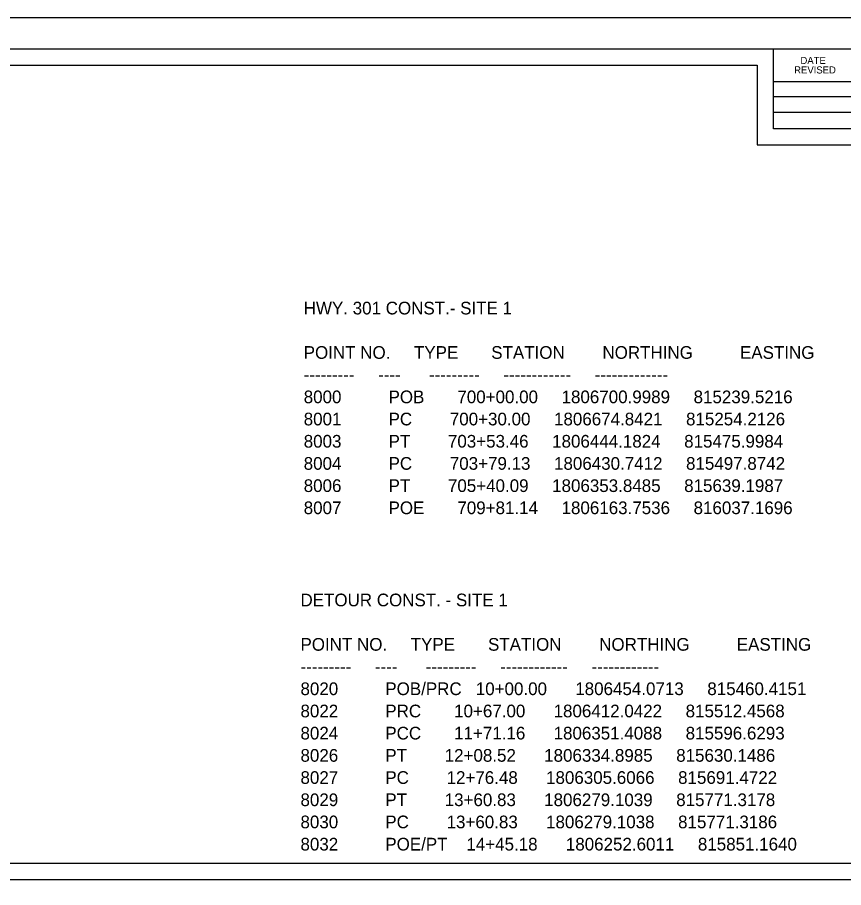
# Model space of a CAD drawing. Extents: x 818639 to 819473, y 1805980 to 1806194.
# Drawn here: x 818811.6 to 818913.8, y 1806086 to 1806193.7 of the extents above; entities that cross this region are included whole.
import ezdxf

# ---------------------------------------------------------------- set-up
doc = ezdxf.new("R2010")
doc.units = 0
for name, color, linetype in [('R_Border', 7, 'Continuous'), ('R_Border Plan-Plan', 7, 'Continuous'), ('R_Draft', 7, 'Continuous'), ('R_No Plot', 7, 'Continuous')]:
    doc.layers.add(name, color=color, linetype=linetype)

msp = doc.modelspace()

# ---------------------------------------------------------------- linework, layer by layer
at = {"layer": 'R_Border'}
for p, q in [((818651.6, 1806189.77), (818967.78, 1806189.77)), ((818905.14, 1806179.89), (818905.14, 1806189.77)), ((818905.14, 1806185.75), (818924.68, 1806185.75)), ((818905.14, 1806183.89), (818924.68, 1806183.89)), ((818905.14, 1806181.95), (818924.68, 1806181.95)), ((818967.78, 1806179.89), (818905.14, 1806179.89))]:
    msp.add_line(p, q, dxfattribs=at)
at = {"layer": 'R_Border Plan-Plan'}
msp.add_line((818651.6, 1806087.04), (818967.78, 1806087.04), dxfattribs=at)
at = {"layer": 'R_No Plot'}
for points in [[(818639.19, 1806193.67), (818972.53, 1806193.67), (818972.53, 1805980.33), (818639.19, 1805980.33)], [(818965.78, 1806089.04), (818653.6, 1806089.04), (818653.6, 1806187.77), (818903.14, 1806187.77), (818903.14, 1806177.89), (818920.68, 1806177.89), (818944.78, 1806177.89), (818944.78, 1806155.56), (818965.78, 1806155.56)], [(818653.6, 1806187.77), (818903.14, 1806187.77), (818903.14, 1806177.89), (818920.68, 1806177.89), (818944.78, 1806177.89), (818944.78, 1806155.56), (818965.78, 1806155.56), (818965.78, 1805986.31), (818653.6, 1805986.31)]]:
    msp.add_lwpolyline(points, close=True, dxfattribs=at)

# ---------------------------------------------------------------- texts
at = {"layer": 'R_Border'}
for s, p in [('DATE', (818908.48, 1806187.91)), ('REVISED', (818907.7, 1806186.73))]:
    msp.add_text(s, height=0.879, dxfattribs=at).set_placement(p)
at = {"layer": 'R_Draft'}
for s, p in [('HWY. 301 CONST.- SITE 1 ', (818847.04, 1806156.93)), ('POINT NO.     TYPE       STATION        NORTHING          EASTING ', (818847.04, 1806151.44)), ('---------     ----      ---------     ------------     -------------', (818847.04, 1806148.7)), ('8000          POB       700+00.00     1806700.9989     815239.5216', (818847.04, 1806145.95)), ('8001          PC        700+30.00     1806674.8421     815254.2126', (818847.04, 1806143.21)), ('8003          PT        703+53.46     1806444.1824     815475.9984', (818847.04, 1806140.46)), ('8004          PC        703+79.13     1806430.7412     815497.8742', (818847.04, 1806137.72)), ('8006          PT        705+40.09     1806353.8485     815639.1987', (818847.04, 1806134.97)), ('8007          POE       709+81.14     1806163.7536     816037.1696', (818847.04, 1806132.23)), ('DETOUR CONST. - SITE 1', (818846.64, 1806120.83)), ('POINT NO.     TYPE       STATION        NORTHING          EASTING ', (818846.64, 1806115.34)), ('---------     ----      ---------     ------------     ------------ ', (818846.64, 1806112.6)), ('8020          POB/PRC   10+00.00      1806454.0713     815460.4151 ', (818846.64, 1806109.85)), ('8022          PRC       10+67.00      1806412.0422     815512.4568', (818846.64, 1806107.1)), ('8024          PCC       11+71.16      1806351.4088     815596.6293', (818846.64, 1806104.36)), ('8026          PT        12+08.52      1806334.8985     815630.1486', (818846.64, 1806101.61)), ('8027          PC        12+76.48      1806305.6066     815691.4722', (818846.64, 1806098.87)), ('8029          PT        13+60.83      1806279.1039     815771.3178', (818846.64, 1806096.12)), ('8030          PC        13+60.83      1806279.1038     815771.3186', (818846.64, 1806093.38)), ('8032          POE/PT    14+45.18      1806252.6011     815851.1640', (818846.64, 1806090.63))]:
    msp.add_text(s, height=1.5686, dxfattribs=at).set_placement(p)

doc.saveas('drawing.dxf')
